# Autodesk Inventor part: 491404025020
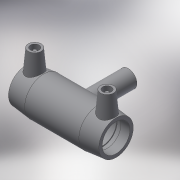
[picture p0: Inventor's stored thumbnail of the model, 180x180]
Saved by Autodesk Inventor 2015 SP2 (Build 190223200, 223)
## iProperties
Created: 2017-06
Part Number: 491404025020
Material: Generic
Description: PLASSON REDUCING TEE 25x20x25
Document SubType Name: Modeling
Designer: KIM
Mass: 57.3761 g
Surface Area: 241.06 cm^2
Volume: 57.3761 cm^3
Density: 1 g/cm^3
Appearance: Default
Author: KIM
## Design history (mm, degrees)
derived "491404.ipt"
feature "Solid1::491404.ipt"
tag "TaggingFeature1"
body "Solid1"
other parameters: "d0" = 104, "d1" = 25, "d2" = 44, "d3" = 39, "d4" = 20.8, "d5" = 39.6, "d6" = 23.75, "d7" = 25, "d8" = 168 deg, "d10" = 15.6, "d11" = 5.2, "d13" = 104, "d14" = 17.6296, "d17" = 22.5, "d18" = 25, "d19" = 3.52592, "d20" = 168 deg, "d22" = 40.92, "d23" = 44, "d25" = 135 deg, "d26" = 72.8, "d29" = 43, "d30" = 15, "d31" = 41.6, "d34" = 5 deg, "d35" = 15, "d39" = 5 deg, "d41" = 4, "d42" = 14, "d43" = 0, "d45" = 4, "d46" = 6, "d47" = 0, "d48" = -66, "d51" = 0, "d52" = 16, "d54" = 0, "d55" = 39.6, "d56" = 44, "d57" = 36.4, "d58" = 135 deg, "d59" = 39, "d60" = 39, "d61" = 135 deg, "d62" = 66, "d72" = 47.32, "d73" = 23.66, "d74" = -66, "d75" = 21, "d77" = 0, "d78" = 16, "d80" = 0, "d82" = 44, "d83" = 0, "d84" = 3, "d85" = 0, "d86" = 13, "d87" = 40.1016, "d88" = 5.2, "d89" = 3, "d90" = 0, "d_" = 25, "L_" = 104, "L_1" = 39, "D_" = 44, "A_" = 43, "d_2" = 12, "H_" = 66
